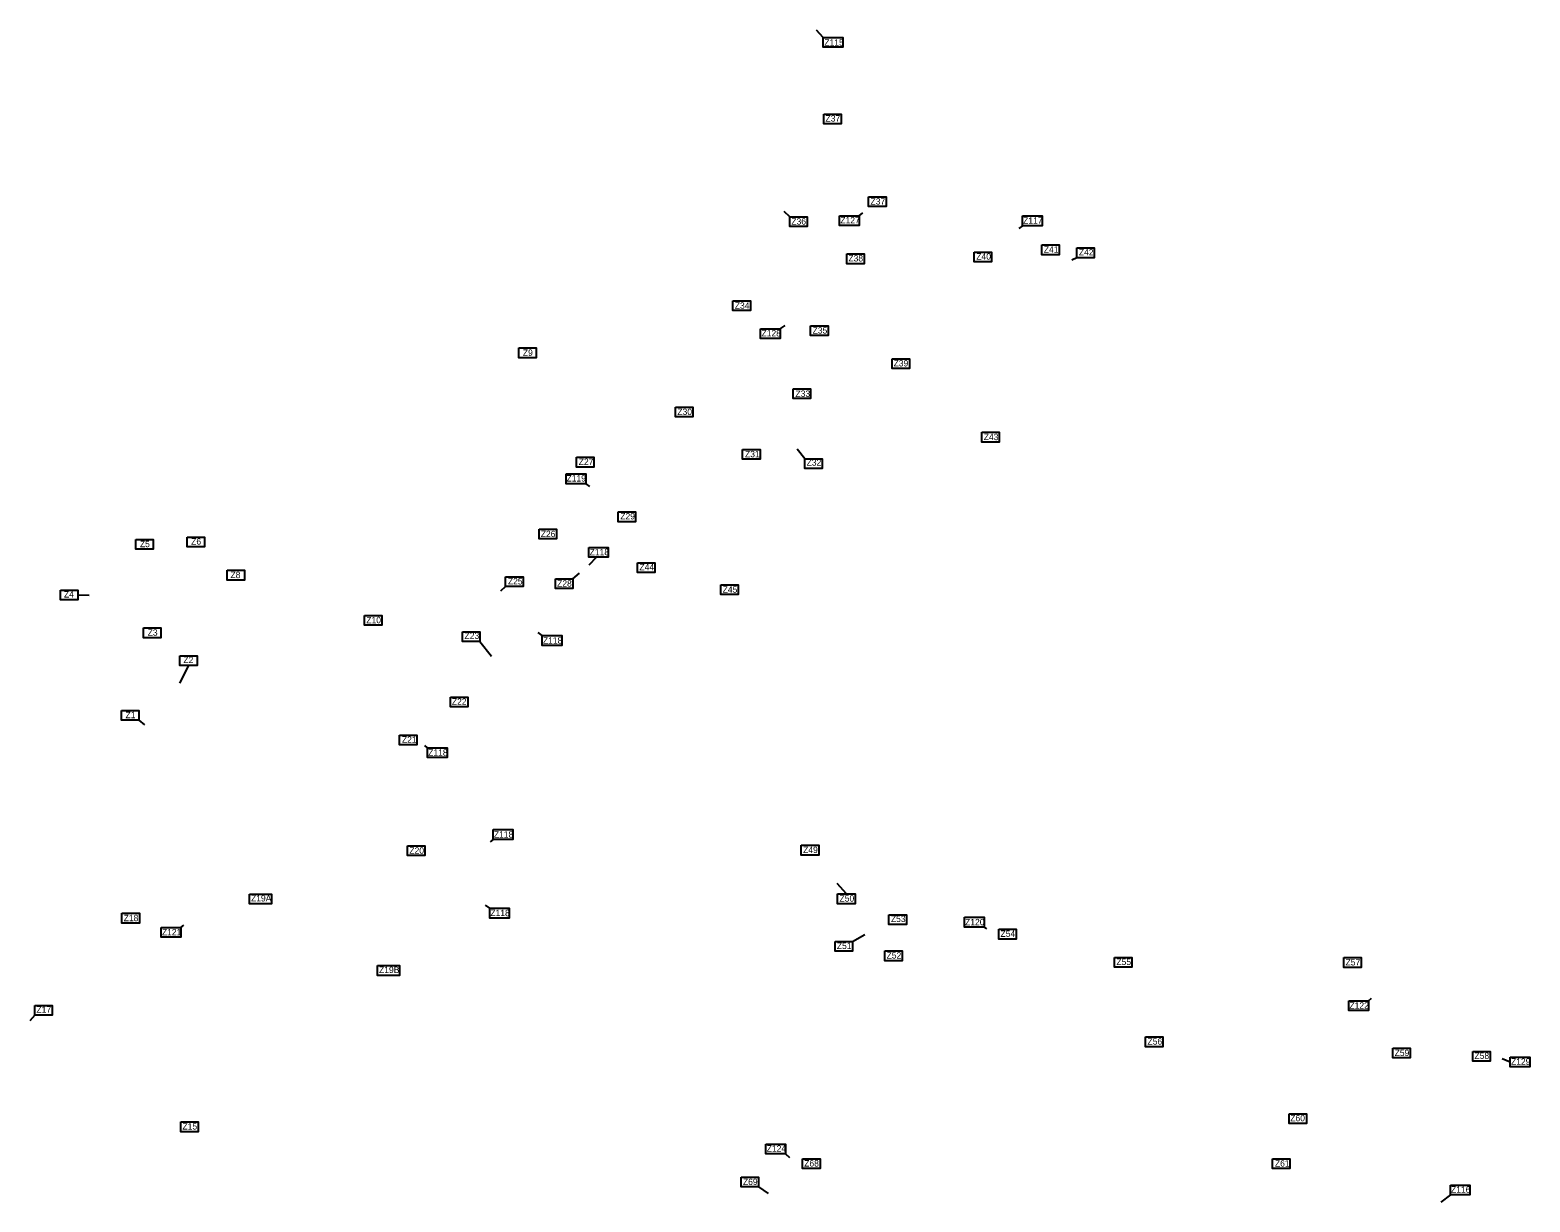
# Model space of a CAD drawing. Extents: x -443485 to -434416, y -1135265 to -1129797.
# Drawn here: x -443022 to -440666, y -1131638 to -1129797 of the extents above; entities that cross this region are included whole.
import ezdxf

# ---------------------------------------------------------------- set-up
doc = ezdxf.new("R2010")
doc.units = 0
doc.layers.add('Vrstva 3', color=7, linetype='Continuous')
doc.layers.add('Vrstva 8', color=7, linetype='Continuous')

msp = doc.modelspace()

# ---------------------------------------------------------------- linework, layer by layer
at = {"layer": 'Vrstva 3'}
for p, q in [((-441776.5, -1129808.4), (-441787.2, -1129796.7)), ((-441829.1, -1130090.3), (-441838, -1130081.7)), ((-441378.1, -1130154.6), (-441386.2, -1130158.4)), ((-441805.4, -1130470.4), (-441817.3, -1130455.4)), ((-442169.8, -1130659.1), (-442159.4, -1130650.4)), ((-442275.3, -1130671.3), (-442283.1, -1130678.3)), ((-442947.3, -1130684.5), (-442929.2, -1130684.8)), ((-442315.6, -1130757.6), (-442297.5, -1130780.5)), ((-442773.4, -1130795.3), (-442787.4, -1130823.1)), ((-442851.5, -1130881.4), (-442842.3, -1130888.4)), ((-441740.1, -1131154.3), (-441754.6, -1131137.8)), ((-441730.2, -1131228.8), (-441711, -1131218.2)), ((-443014.7, -1131344.8), (-443022.4, -1131353.5)), ((-441878.2, -1131614.7), (-441862.9, -1131625)), ((-440791.4, -1131627.3), (-440806.3, -1131638.4))]:
    msp.add_line(p, q, dxfattribs=at)
for points in [[(-441776.5, -1129808.4), (-441745.7, -1129808.4), (-441745.7, -1129823.8), (-441776.5, -1129823.8)], [(-441775.4, -1129929), (-441748, -1129929), (-441748, -1129944.4), (-441775.4, -1129944.4)], [(-441705.1, -1130058.7), (-441677.7, -1130058.7), (-441677.7, -1130074.1), (-441705.1, -1130074.1)], [(-441829.1, -1130090.3), (-441801.8, -1130090.3), (-441801.8, -1130105.7), (-441829.1, -1130105.7)], [(-441433.1, -1130134.4), (-441405.7, -1130134.4), (-441405.7, -1130149.8), (-441433.1, -1130149.8)], [(-441739.6, -1130148.5), (-441712.2, -1130148.5), (-441712.2, -1130163.9), (-441739.6, -1130163.9)], [(-441539.4, -1130145.7), (-441512, -1130145.7), (-441512, -1130161.1), (-441539.4, -1130161.1)], [(-441378.1, -1130139.2), (-441350.7, -1130139.2), (-441350.7, -1130154.6), (-441378.1, -1130154.6)], [(-441918.2, -1130222.1), (-441890.9, -1130222.1), (-441890.9, -1130237.5), (-441918.2, -1130237.5)], [(-441796.3, -1130261.6), (-441768.9, -1130261.6), (-441768.9, -1130277), (-441796.3, -1130277)], [(-442254.8, -1130296.3), (-442227.5, -1130296.3), (-442227.5, -1130311.7), (-442254.8, -1130311.7)], [(-441668.4, -1130313.2), (-441641, -1130313.2), (-441641, -1130328.6), (-441668.4, -1130328.6)], [(-441823.7, -1130360.6), (-441796.4, -1130360.6), (-441796.4, -1130376), (-441823.7, -1130376)], [(-442008.5, -1130389.3), (-441981.2, -1130389.3), (-441981.2, -1130404.7), (-442008.5, -1130404.7)], [(-441527.5, -1130428.9), (-441500.2, -1130428.9), (-441500.2, -1130444.3), (-441527.5, -1130444.3)], [(-441903, -1130455.8), (-441875.6, -1130455.8), (-441875.6, -1130471.2), (-441903, -1130471.2)], [(-442163.9, -1130468.1), (-442136.5, -1130468.1), (-442136.5, -1130483.5), (-442163.9, -1130483.5)], [(-441805.4, -1130470.4), (-441778, -1130470.4), (-441778, -1130485.8), (-441805.4, -1130485.8)], [(-442098.4, -1130554.1), (-442071.1, -1130554.1), (-442071.1, -1130569.5), (-442098.4, -1130569.5)], [(-442222.8, -1130581.2), (-442195.5, -1130581.2), (-442195.5, -1130596.5), (-442222.8, -1130596.5)], [(-442856.3, -1130597.4), (-442828.9, -1130597.4), (-442828.9, -1130612.7), (-442856.3, -1130612.7)], [(-442775.7, -1130593.4), (-442748.3, -1130593.4), (-442748.3, -1130608.8), (-442775.7, -1130608.8)], [(-442712.8, -1130645.6), (-442685.5, -1130645.6), (-442685.5, -1130661), (-442712.8, -1130661)], [(-442068.4, -1130633.9), (-442041.1, -1130633.9), (-442041.1, -1130649.3), (-442068.4, -1130649.3)], [(-442275.3, -1130655.9), (-442247.9, -1130655.9), (-442247.9, -1130671.3), (-442275.3, -1130671.3)], [(-442197.1, -1130659.1), (-442169.8, -1130659.1), (-442169.8, -1130674.5), (-442197.1, -1130674.5)], [(-441937.3, -1130668.5), (-441909.9, -1130668.5), (-441909.9, -1130683.9), (-441937.3, -1130683.9)], [(-442974.7, -1130676.8), (-442947.3, -1130676.8), (-442947.3, -1130692.2), (-442974.7, -1130692.2)], [(-442497.1, -1130716.5), (-442469.7, -1130716.5), (-442469.7, -1130731.9), (-442497.1, -1130731.9)], [(-442844.2, -1130736.3), (-442816.9, -1130736.3), (-442816.9, -1130751.7), (-442844.2, -1130751.7)], [(-442343, -1130742.2), (-442315.6, -1130742.2), (-442315.6, -1130757.6), (-442343, -1130757.6)], [(-442787.1, -1130779.9), (-442759.7, -1130779.9), (-442759.7, -1130795.3), (-442787.1, -1130795.3)], [(-442362, -1130845), (-442334.6, -1130845), (-442334.6, -1130860.4), (-442362, -1130860.4)], [(-442878.9, -1130866.1), (-442851.5, -1130866.1), (-442851.5, -1130881.4), (-442878.9, -1130881.4)], [(-442441.8, -1130904.7), (-442414.5, -1130904.7), (-442414.5, -1130920.1), (-442441.8, -1130920.1)], [(-442429.5, -1131078.6), (-442402.1, -1131078.6), (-442402.1, -1131094), (-442429.5, -1131094)], [(-441810.9, -1131077.7), (-441783.5, -1131077.7), (-441783.5, -1131093.1), (-441810.9, -1131093.1)], [(-442677.7, -1131154.6), (-442643.2, -1131154.6), (-442643.2, -1131170), (-442677.7, -1131170)], [(-441753.8, -1131154.3), (-441726.4, -1131154.3), (-441726.4, -1131169.7), (-441753.8, -1131169.7)], [(-442877.9, -1131184.7), (-442850.5, -1131184.7), (-442850.5, -1131200.1), (-442877.9, -1131200.1)], [(-441673.2, -1131186.9), (-441645.8, -1131186.9), (-441645.8, -1131202.2), (-441673.2, -1131202.2)], [(-441500.6, -1131209.7), (-441473.3, -1131209.7), (-441473.3, -1131225.1), (-441500.6, -1131225.1)], [(-441757.5, -1131228.8), (-441730.2, -1131228.8), (-441730.2, -1131244.2), (-441757.5, -1131244.2)], [(-441679.9, -1131243.9), (-441652.6, -1131243.9), (-441652.6, -1131259.3), (-441679.9, -1131259.3)], [(-441319, -1131254), (-441291.6, -1131254), (-441291.6, -1131269.4), (-441319, -1131269.4)], [(-440958.8, -1131254.3), (-440931.4, -1131254.3), (-440931.4, -1131269.7), (-440958.8, -1131269.7)], [(-442476.8, -1131266.9), (-442441.8, -1131266.9), (-442441.8, -1131282.3), (-442476.8, -1131282.3)], [(-443014.7, -1131329.4), (-442987.3, -1131329.4), (-442987.3, -1131344.8), (-443014.7, -1131344.8)], [(-441270.2, -1131379), (-441242.8, -1131379), (-441242.8, -1131394.4), (-441270.2, -1131394.4)], [(-440882, -1131396.5), (-440854.6, -1131396.5), (-440854.6, -1131411.9), (-440882, -1131411.9)], [(-440756.3, -1131401.9), (-440728.9, -1131401.9), (-440728.9, -1131417.3), (-440756.3, -1131417.3)], [(-441044.5, -1131499.6), (-441017.1, -1131499.6), (-441017.1, -1131515), (-441044.5, -1131515)], [(-442785.3, -1131512.6), (-442758, -1131512.6), (-442758, -1131528), (-442785.3, -1131528)], [(-441808.9, -1131570.5), (-441781.5, -1131570.5), (-441781.5, -1131585.9), (-441808.9, -1131585.9)], [(-441070.7, -1131570.5), (-441043.3, -1131570.5), (-441043.3, -1131585.9), (-441070.7, -1131585.9)], [(-441905.5, -1131599.3), (-441878.2, -1131599.3), (-441878.2, -1131614.7), (-441905.5, -1131614.7)], [(-440791.4, -1131611.9), (-440760.7, -1131611.9), (-440760.7, -1131627.3), (-440791.4, -1131627.3)]]:
    msp.add_lwpolyline(points, close=True, dxfattribs=at)
at = {"layer": 'Vrstva 8'}
for p, q in [((-441720.1, -1130088.6), (-441714.3, -1130084)), ((-441463.6, -1130104.2), (-441469.4, -1130108.5)), ((-441844, -1130266.2), (-441836.1, -1130260.9)), ((-442149.3, -1130509.6), (-442143.6, -1130514.2)), ((-442132.8, -1130625.1), (-442144.7, -1130637.5)), ((-442217.8, -1130748.4), (-442224.2, -1130743.6)), ((-442398, -1130924.7), (-442402.3, -1130921.1)), ((-442294.8, -1131068.6), (-442299.8, -1131072.4)), ((-442300.3, -1131176.7), (-442306.7, -1131171.9)), ((-442785.3, -1131206.9), (-442780.8, -1131203.4)), ((-441523.9, -1131206.4), (-441520.2, -1131209.2)), ((-440920.2, -1131322), (-440915.5, -1131317.9)), ((-440697.5, -1131418.4), (-440709.9, -1131413.3)), ((-441835.8, -1131562.7), (-441829.5, -1131568.4))]:
    msp.add_line(p, q, dxfattribs=at)
for points in [[(-441750.9, -1130088.6), (-441720.1, -1130088.6), (-441720.1, -1130104), (-441750.9, -1130104)], [(-441463.6, -1130088.8), (-441432.8, -1130088.8), (-441432.8, -1130104.2), (-441463.6, -1130104.2)], [(-441463.6, -1130088.8), (-441432.8, -1130088.8), (-441432.8, -1130104.2), (-441463.6, -1130104.2)], [(-441874.8, -1130266.2), (-441844, -1130266.2), (-441844, -1130281.6), (-441874.8, -1130281.6)], [(-442180.1, -1130494.2), (-442149.3, -1130494.2), (-442149.3, -1130509.6), (-442180.1, -1130509.6)], [(-442144.8, -1130609.7), (-442114, -1130609.7), (-442114, -1130625.1), (-442144.8, -1130625.1)], [(-442217.8, -1130748.4), (-442187, -1130748.4), (-442187, -1130763.8), (-442217.8, -1130763.8)], [(-442398, -1130924.7), (-442367.2, -1130924.7), (-442367.2, -1130940.1), (-442398, -1130940.1)], [(-442294.8, -1131053.2), (-442264, -1131053.2), (-442264, -1131068.6), (-442294.8, -1131068.6)], [(-442300.3, -1131176.7), (-442269.5, -1131176.7), (-442269.5, -1131192.1), (-442300.3, -1131192.1)], [(-441554.7, -1131191), (-441523.9, -1131191), (-441523.9, -1131206.4), (-441554.7, -1131206.4)], [(-442816.1, -1131206.9), (-442785.3, -1131206.9), (-442785.3, -1131222.3), (-442816.1, -1131222.3)], [(-440951, -1131322), (-440920.2, -1131322), (-440920.2, -1131337.4), (-440951, -1131337.4)], [(-440697.5, -1131410.7), (-440666.8, -1131410.7), (-440666.8, -1131426.1), (-440697.5, -1131426.1)], [(-441866.6, -1131547.3), (-441835.8, -1131547.3), (-441835.8, -1131562.7), (-441866.6, -1131562.7)]]:
    msp.add_lwpolyline(points, close=True, dxfattribs=at)

# ---------------------------------------------------------------- texts
at = {"layer": 'Vrstva 3'}
for s, p in [('Z115', (-441774.7, -1129821.3)), ('Z37', (-441772.8, -1129940.6)), ('Z37', (-441702.1, -1130071)), ('Z36', (-441826.5, -1130102.5)), ('Z38', (-441736.9, -1130160.4)), ('Z40', (-441536, -1130157.5)), ('Z41', (-441430, -1130146.8)), ('Z42', (-441374.9, -1130151)), ('Z34', (-441915.3, -1130234.7)), ('Z35', (-441793.1, -1130273.7)), ('Z9', (-442248.2, -1130308.7)), ('Z39', (-441665.9, -1130325.4)), ('Z33', (-441820, -1130373.2)), ('Z30', (-442005.5, -1130401.6)), ('Z43', (-441524.3, -1130441.2)), ('Z31', (-441899.3, -1130468.1)), ('Z27', (-442160.4, -1130480.1)), ('Z32', (-441802.5, -1130481.3)), ('Z29', (-442095.2, -1130565.8)), ('Z5', (-442849.7, -1130609.4)), ('Z6', (-442769.2, -1130605.4)), ('Z26', (-442220.1, -1130593.6)), ('Z8', (-442707.5, -1130658)), ('Z44', (-442065.1, -1130645.7)), ('Z25', (-442271.7, -1130668)), ('Z28', (-442194.4, -1130671.3)), ('Z45', (-441934.4, -1130681)), ('Z4', (-442969.1, -1130688.5)), ('Z10', (-442494.1, -1130728.9)), ('Z3', (-442837.5, -1130748.5)), ('Z23', (-442339.8, -1130753.5)), ('Z2', (-442781.4, -1130791.5)), ('Z22', (-442359.7, -1130857.1)), ('Z1', (-442872.3, -1130878.1)), ('Z21', (-442438.2, -1130916.8)), ('Z20', (-442426.5, -1131091.1)), ('Z49', (-441808, -1131090)), ('Z19A', (-442675.2, -1131166.1)), ('Z50', (-441750.8, -1131166.3)), ('Z18', (-442875.2, -1131197.1)), ('Z53', (-441670.1, -1131198.5)), ('Z54', (-441497.9, -1131221.7)), ('Z51', (-441755, -1131240.9)), ('Z52', (-441676.9, -1131255.8)), ('Z55', (-441315.9, -1131266)), ('Z57', (-440956, -1131266.7)), ('Z19B', (-442474.1, -1131278.6)), ('Z17', (-443012.2, -1131341)), ('Z56', (-441267.1, -1131391.1)), ('Z59', (-440878.9, -1131409)), ('Z58', (-440753.5, -1131413.6)), ('Z15', (-442782.9, -1131524.5)), ('Z60', (-441042.8, -1131511.5)), ('Z68', (-441806.3, -1131582.6)), ('Z61', (-441066.9, -1131582.7)), ('Z69', (-441902.5, -1131611.6)), ('Z116', (-440790.4, -1131623.8))]:
    msp.add_text(s, height=10, dxfattribs=at).set_placement(p)
at = {"layer": 'Vrstva 8'}
for s, p in [('Z127', (-441749.5, -1130100.6)), ('Z117', (-441462.5, -1130101.2)), ('Z128', (-441873.4, -1130278.2)), ('Z119', (-442179.6, -1130506.2)), ('Z118', (-442143.3, -1130622)), ('Z118', (-442216.7, -1130760.9)), ('Z118', (-442396.9, -1130937.1)), ('Z118', (-442293.7, -1131065.7)), ('Z118', (-442299.3, -1131189.2)), ('Z120', (-441553.6, -1131203.5)), ('Z121', (-442815.1, -1131219.3)), ('Z122', (-440949.9, -1131334.5)), ('Z129', (-440696.1, -1131422.7)), ('Z124', (-441865.2, -1131559.3))]:
    msp.add_text(s, height=10, dxfattribs=at).set_placement(p)

doc.saveas('drawing.dxf')
